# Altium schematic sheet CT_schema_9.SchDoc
size 226 x 144 mm
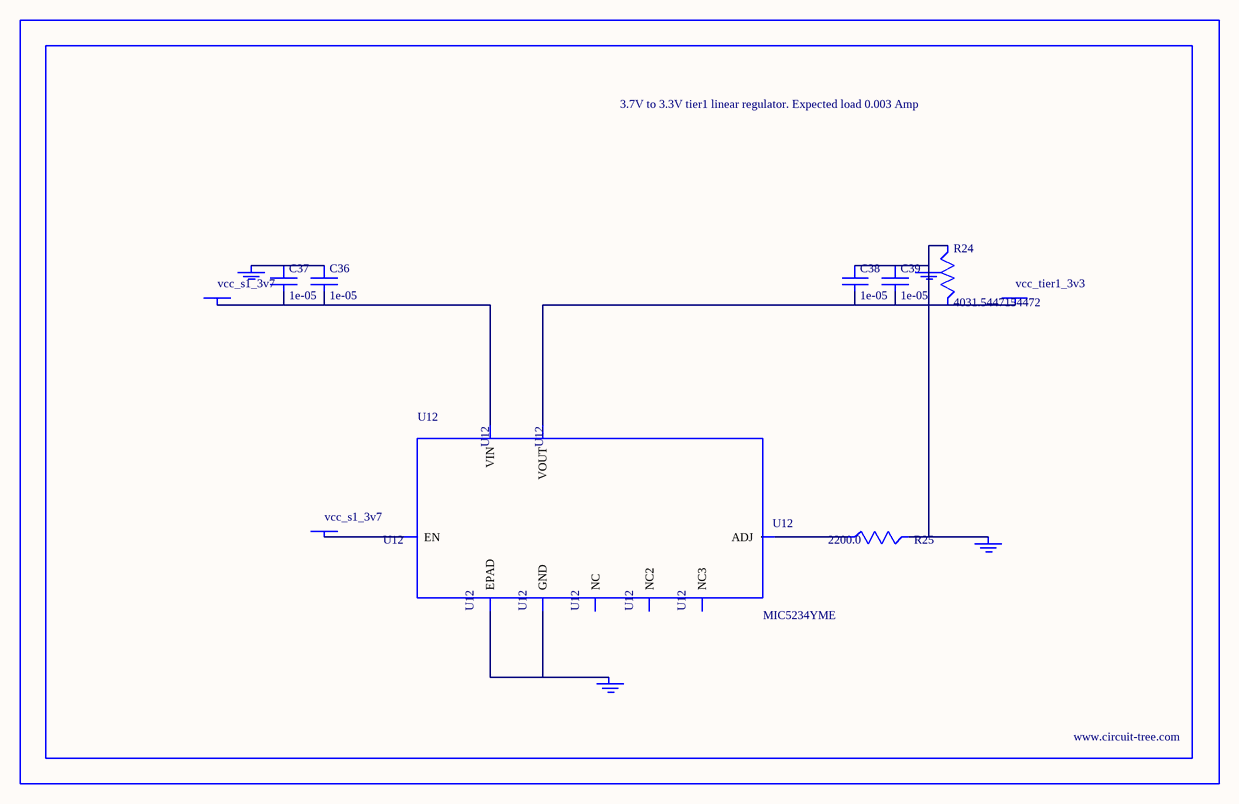
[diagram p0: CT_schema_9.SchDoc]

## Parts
BORDER8  (no value)
C36  1e-05  [C1210]
C37  1e-05  [C1210]
C38  1e-05  [C1210]
C39  1e-05  [C1210]
GND_INSTANCE_8_0  (no value)
GND_INSTANCE_8_1  (no value)
GND_INSTANCE_8_2  (no value)
GND_INSTANCE_8_3  (no value)
POWER_INSTANCE_8_0  vcc_tier1_3v3
POWER_INSTANCE_8_1  vcc_s1_3v7
POWER_INSTANCE_8_2  vcc_s1_3v7
R24  4031.5447154472  [R0603]
R25  2200.0  [R0603]
U12  MIC5234YME  [SOIC-8_EP]

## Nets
NetC36_1: C36.1 C37.1 GND_INSTANCE_8_3.0(GND)
NetC36_2: C36.2 C37.2 POWER_INSTANCE_8_2.0(PWR) U12.8(VIN)
NetC38_1: C38.1 C39.1 GND_INSTANCE_8_0.0(GND) GND_INSTANCE_8_1.0(GND) R24.1 R25.2
NetC38_2: C38.2 C39.2 POWER_INSTANCE_8_0.0(PWR) R24.2 U12.1(VOUT)
NetGND_INSTANCE_8_2_0: GND_INSTANCE_8_2.0(GND) U12.7(GND) U12.EPAD
NetPOWER_INSTANCE_8_1_0: POWER_INSTANCE_8_1.0(PWR) U12.5(EN)
NetR25_1: R25.1 U12.4(ADJ)

Not connected (* = marked no-connect by the designer): U12 2(NC) 3(NC2) 6(NC3)

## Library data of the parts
BORDER8 = BORDER_PAGE8
C36-C39 = C1210C106K5PACTU
GND_INSTANCE_8_0-GND_INSTANCE_8_3 = GND
POWER_INSTANCE_8_0-POWER_INSTANCE_8_2 = PWR
R24 = R24
R25 = RC0603JR-072K2L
